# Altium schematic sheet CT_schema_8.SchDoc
size 391 x 238 mm
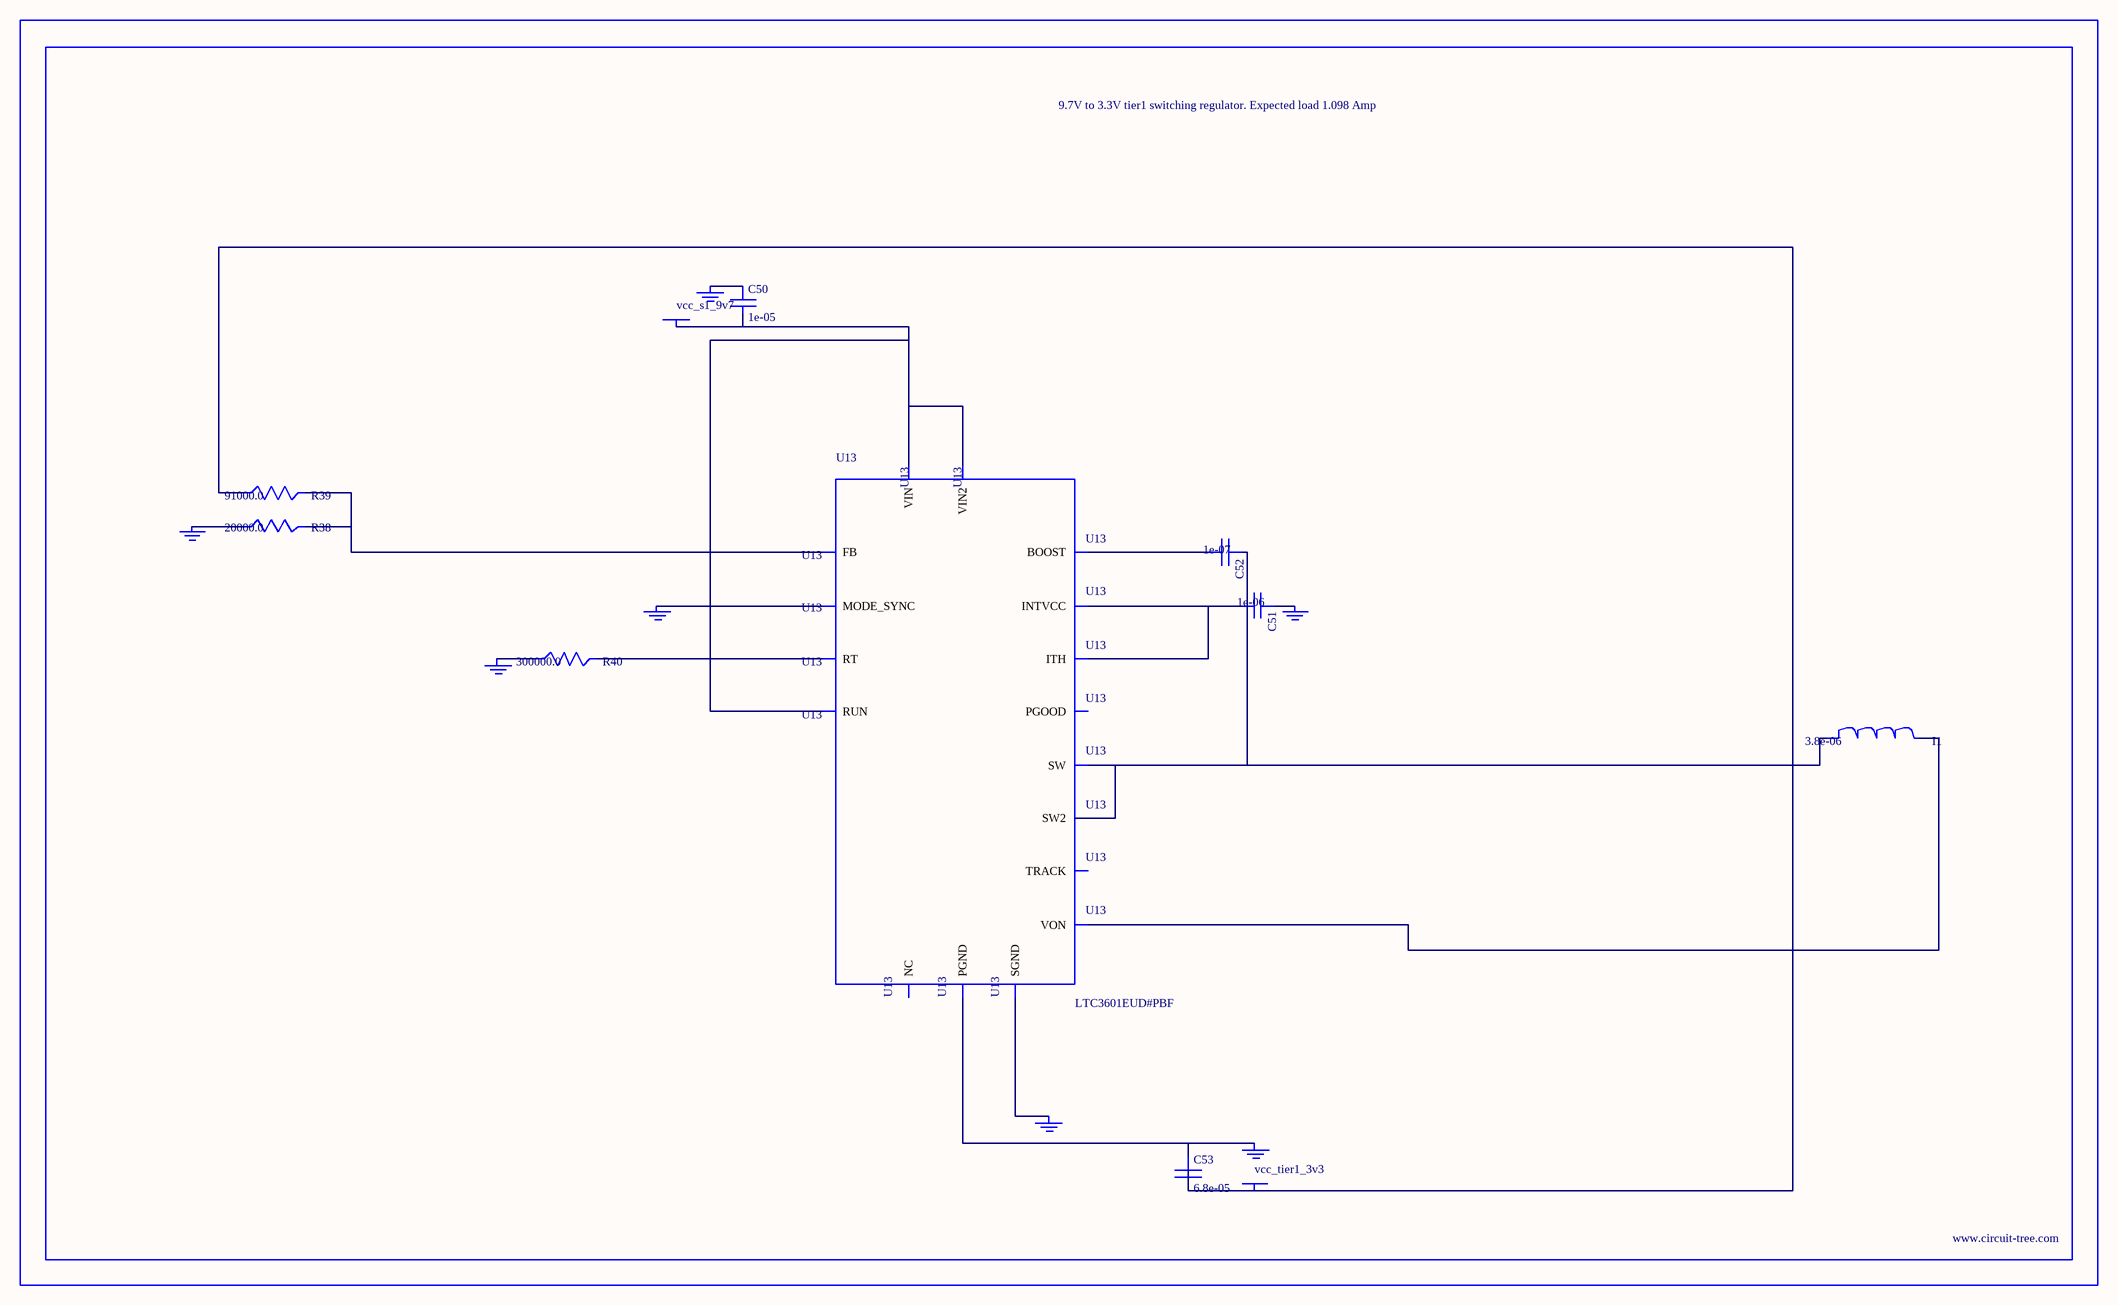
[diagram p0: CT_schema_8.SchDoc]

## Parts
BORDER7  (no value)
C50  1e-05  [C0805]
C51  1e-06  [C0603]
C52  1e-07  [C0402]
C53  6.8e-05  [2220]
GND_INSTANCE_7_0  (no value)
GND_INSTANCE_7_1  (no value)
GND_INSTANCE_7_2  (no value)
GND_INSTANCE_7_3  (no value)
GND_INSTANCE_7_4  (no value)
GND_INSTANCE_7_5  (no value)
GND_INSTANCE_7_6  (no value)
I1  3.8e-06  [DR1040]
POWER_INSTANCE_7_0  vcc_s1_9v7
POWER_INSTANCE_7_1  vcc_tier1_3v3
R38  20000.0  [R0603]
R39  91000.0  [R0603]
R40  300000.0  [R0603]
U13  LTC3601EUD#PBF  [QFN-16_EP]

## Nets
NetC50_1: C50.1 GND_INSTANCE_7_5.0(GND)
NetC50_2: C50.2 POWER_INSTANCE_7_0.0(PWR) U13.14(RUN) U13.15(VIN) U13.16(VIN2)
NetC51_1: C51.1 GND_INSTANCE_7_1.0(GND)
NetC51_2: C51.2 U13.7(INTVCC) U13.12(ITH)
NetC52_1: C52.1 I1.1 U13.3(SW) U13.4(SW2)
NetC52_2: C52.2 U13.6(BOOST)
NetC53_1: C53.1 GND_INSTANCE_7_6.0(GND) U13.17(PGND)
NetC53_2: C53.2 I1.2 POWER_INSTANCE_7_1.0(PWR) R39.1 U13.8(VON)
NetGND_INSTANCE_7_0_0: GND_INSTANCE_7_0.0(GND) U13.1(MODE_SYNC)
NetGND_INSTANCE_7_2_0: GND_INSTANCE_7_2.0(GND) U13.9(SGND)
NetGND_INSTANCE_7_3_0: GND_INSTANCE_7_3.0(GND) R40.1
NetGND_INSTANCE_7_4_0: GND_INSTANCE_7_4.0(GND) R38.1
NetR38_2: R38.2 R39.2 U13.11(FB)
NetR40_2: R40.2 U13.10(RT)

Not connected (* = marked no-connect by the designer): U13 2(PGOOD) 5(NC) 13(TRACK)

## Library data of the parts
BORDER7 = BORDER_PAGE7
C50 = C0805C106K8RACTU
C51 = C0603C105K3RACTU
C52 = C0402C104K3RACTU
C53 = C5750X5R1A686M
GND_INSTANCE_7_0-GND_INSTANCE_7_6 = GND
I1 = DR1040-3R8-R
POWER_INSTANCE_7_0 POWER_INSTANCE_7_1 = PWR
R38 = RC0603JR-0720KL
R39 = RC0603JR-0791KL
R40 = RC0603JR-07300KL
